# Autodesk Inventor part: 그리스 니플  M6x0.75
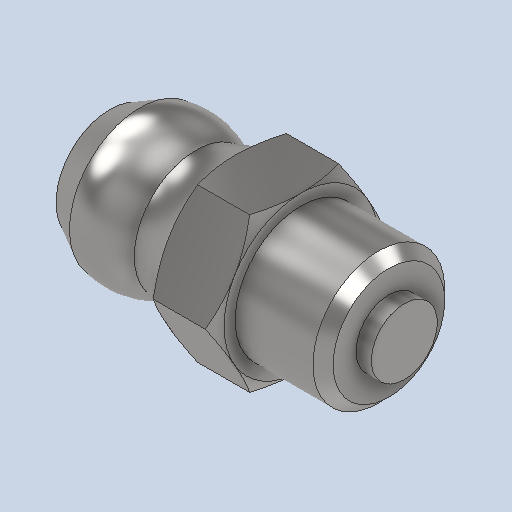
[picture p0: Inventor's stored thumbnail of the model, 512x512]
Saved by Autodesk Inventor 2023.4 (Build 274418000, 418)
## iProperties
Created: 2024-11
Part Number: 그리스 니플  M6x0.75
Material: 강철, 연강
Description: 윤활 니플, 원추 유형 A
Document SubType Name: Modeling
Designer: EDU
Density: 7.85 g/cm^3
Appearance: 기본값
Author: jhkim
Sending System: Autodesk Inventor 2025
Preprocessor: ST-DEVELOPER v20
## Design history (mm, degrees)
feature "Solid1"
node "솔리드1"
